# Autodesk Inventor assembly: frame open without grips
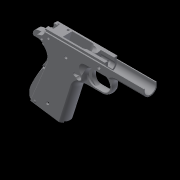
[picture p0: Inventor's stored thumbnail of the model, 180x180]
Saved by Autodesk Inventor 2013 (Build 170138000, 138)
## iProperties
Created: 2013-01
Part Number: frame open without grips
Document SubType Name: Assembly
Designer: John
Author: John
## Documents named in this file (3)
- C:\Users\George\Desktop\1911\frame open without grips.iam
- C:\Users\George\Desktop\1911\1911 frame open (no grips).ipt
- C:\Users\George\Desktop\1911\1911 back grip.ipt
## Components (2 placed, 2 different names)
1. 1911 frame open (no grips):1 — Mate:2, Flush:1
2. 1911 back grip:1 — Mate:2, Flush:1
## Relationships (2: Mate 1, Flush 1)
- Mate:2: 1911 frame open (no grips):1 ↔ 1911 back grip:1
- Flush:1: 1911 frame open (no grips):1 ↔ 1911 back grip:1
